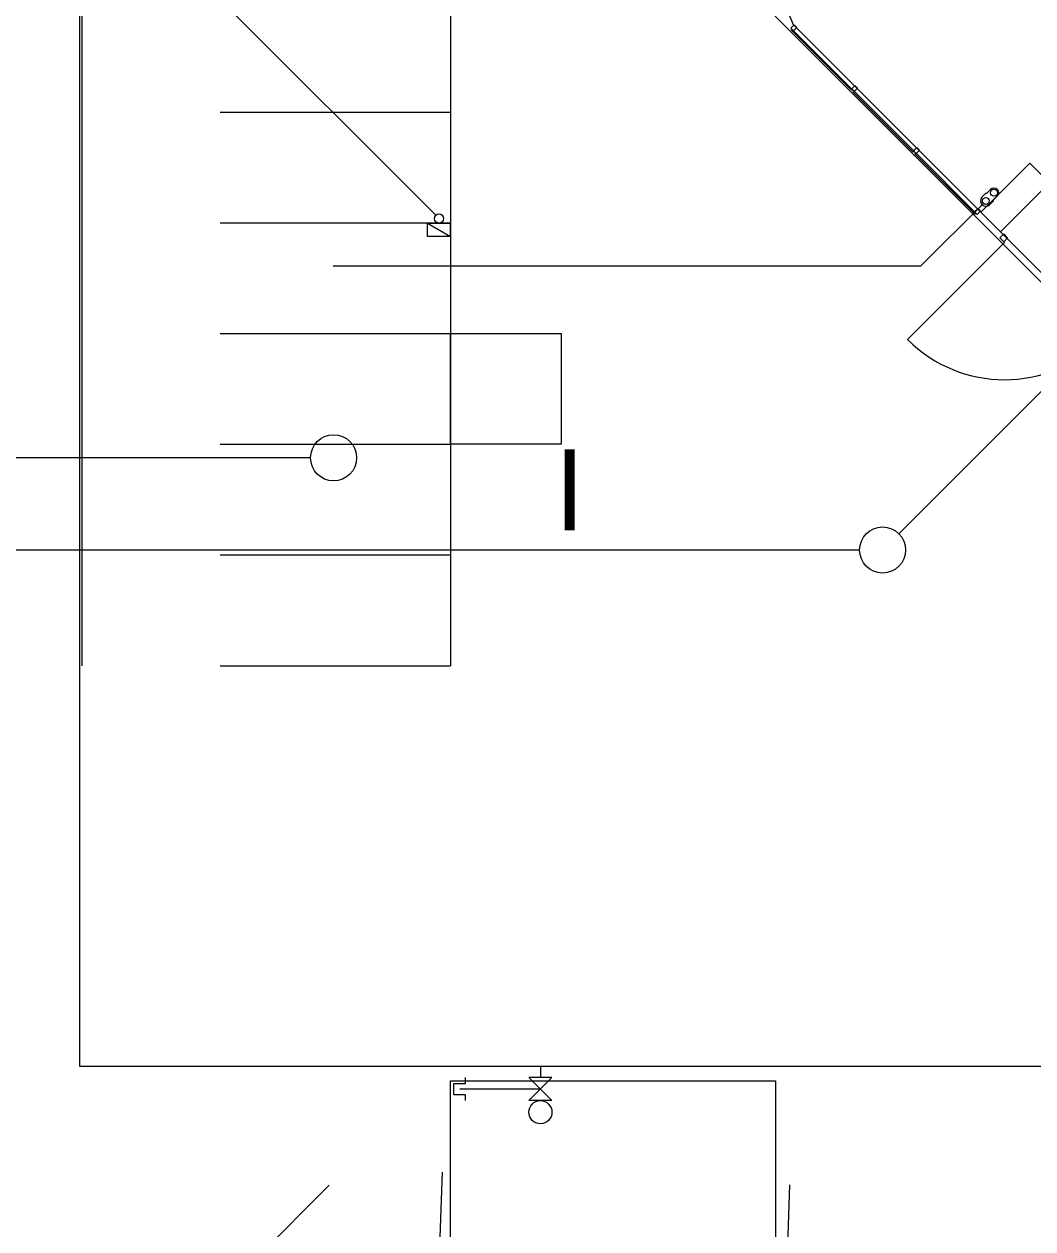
# Model space of a CAD drawing. Extents: x -264205 to -263615, y -1242401 to -1242031.
# Drawn here: x -263925.35 to -263903.46, y -1242253.67 to -1242227.54 of the extents above; entities that cross this region are included whole.
import ezdxf

# ---------------------------------------------------------------- set-up
doc = ezdxf.new("R2010")
doc.units = 0
doc.layers.add('KOORDINACNA_SITUACIA_DSP', color=7, linetype='Continuous')
doc.layers.add('PROJEKT_DRS_TDZ_VODOROVNE', color=7, linetype='Continuous')

msp = doc.modelspace()

# ---------------------------------------------------------------- linework, layer by layer
at = {"layer": 'KOORDINACNA_SITUACIA_DSP'}
for p, q in [((-263924.143, -1242185.14), (-263924.143, -1242250.14)), ((-263889.023, -1242221.253), (-263906.365, -1242238.596)), ((-263916.414, -1242231.691), (-263926.24, -1242221.865)), ((-263908.893, -1242226.995), (-263908.663, -1242227.55)), ((-263908.709, -1242227.631), (-263908.638, -1242227.56)), ((-263908.68, -1242227.659), (-263908.709, -1242227.631)), ((-263908.685, -1242227.654), (-263908.703, -1242227.672)), ((-263908.703, -1242227.672), (-263907.395, -1242228.98)), ((-263907.377, -1242228.963), (-263908.685, -1242227.654)), ((-263908.652, -1242227.688), (-263908.68, -1242227.659)), ((-263908.663, -1242227.55), (-263895.135, -1242241.078)), ((-263908.581, -1242227.617), (-263908.652, -1242227.688)), ((-263908.638, -1242227.56), (-263908.581, -1242227.617)), ((-263907.395, -1242228.98), (-263907.377, -1242228.963)), ((-263907.39, -1242228.95), (-263907.319, -1242228.879)), ((-263907.361, -1242228.978), (-263907.39, -1242228.95)), ((-263907.363, -1242229.012), (-263907.345, -1242228.994)), ((-263906.055, -1242230.32), (-263907.363, -1242229.012)), ((-263907.333, -1242229.007), (-263907.361, -1242228.978)), ((-263907.345, -1242228.994), (-263906.037, -1242230.303)), ((-263907.262, -1242228.936), (-263907.333, -1242229.007)), ((-263907.319, -1242228.879), (-263907.262, -1242228.936)), ((-263906.037, -1242230.303), (-263906.055, -1242230.32)), ((-263906.046, -1242230.294), (-263905.975, -1242230.223)), ((-263906.017, -1242230.322), (-263906.046, -1242230.294)), ((-263906.019, -1242230.356), (-263906.001, -1242230.338)), ((-263905.989, -1242230.351), (-263906.017, -1242230.322)), ((-263906.001, -1242230.338), (-263904.693, -1242231.647)), ((-263905.918, -1242230.28), (-263905.989, -1242230.351)), ((-263905.975, -1242230.223), (-263905.918, -1242230.28)), ((-263904.711, -1242231.664), (-263906.019, -1242230.356)), ((-263903.526, -1242230.561), (-263904.586, -1242231.622)), ((-263903.101, -1242230.985), (-263903.526, -1242230.561)), ((-263904.162, -1242232.046), (-263903.101, -1242230.985)), ((-263904.484, -1242231.218), (-263904.563, -1242231.296)), ((-263904.465, -1242231.218), (-263904.484, -1242231.218)), ((-263904.376, -1242231.13), (-263904.465, -1242231.218)), ((-263904.397, -1242231.462), (-263904.319, -1242231.383)), ((-263904.319, -1242231.383), (-263904.397, -1242231.462)), ((-263904.231, -1242231.275), (-263904.319, -1242231.364)), ((-263904.319, -1242231.364), (-263904.319, -1242231.383)), ((-263904.533, -1242231.432), (-263905.894, -1242232.793)), ((-263904.726, -1242231.613), (-263904.656, -1242231.543)), ((-263904.698, -1242231.642), (-263904.726, -1242231.613)), ((-263904.67, -1242231.67), (-263904.698, -1242231.642)), ((-263904.599, -1242231.599), (-263904.67, -1242231.67)), ((-263904.656, -1242231.543), (-263904.599, -1242231.599)), ((-263904.586, -1242231.622), (-263904.162, -1242232.046)), ((-263916.593, -1242231.862), (-263916.093, -1242231.862)), ((-263916.593, -1242232.152), (-263916.593, -1242231.862)), ((-263916.593, -1242231.862), (-263916.093, -1242232.152)), ((-263916.593, -1242231.862), (-263916.093, -1242232.152)), ((-263916.093, -1242231.862), (-263916.593, -1242231.862)), ((-263916.093, -1242231.862), (-263916.093, -1242232.152)), ((-263916.093, -1242232.152), (-263916.093, -1242231.862)), ((-263904.693, -1242231.647), (-263904.711, -1242231.664)), ((-263916.093, -1242232.152), (-263916.593, -1242232.152)), ((-263904.091, -1242232.093), (-263904.176, -1242232.178)), ((-263904.006, -1242232.178), (-263904.091, -1242232.093)), ((-263904.074, -1242232.281), (-263906.177, -1242234.384)), ((-263904.176, -1242232.178), (-263904.091, -1242232.263)), ((-263904.091, -1242232.263), (-263904.006, -1242232.178)), ((-263904.091, -1242232.263), (-263904.074, -1242232.281)), ((-263905.894, -1242232.793), (-263918.643, -1242232.793)), ((-263916.093, -1242234.257), (-263913.693, -1242234.257)), ((-263916.093, -1242236.657), (-263916.093, -1242234.257)), ((-263913.693, -1242234.257), (-263913.693, -1242236.657)), ((-263913.693, -1242236.657), (-263916.093, -1242236.657)), ((-263919.13, -1242236.949), (-263926.43, -1242236.949)), ((-263907.219, -1242238.949), (-263926.43, -1242238.949)), ((-263924.143, -1242250.14), (-263788.143, -1242250.14)), ((-263914.143, -1242250.14), (-263914.143, -1242250.39)), ((-263914.143, -1242250.14), (-263914.143, -1242250.39)), ((-263915.768, -1242250.515), (-263915.768, -1242250.39)), ((-263914.393, -1242250.39), (-263913.893, -1242250.89)), ((-263913.893, -1242250.39), (-263914.393, -1242250.39)), ((-263914.393, -1242250.89), (-263913.893, -1242250.39)), ((-263916.093, -1242254.982), (-263916.093, -1242250.458)), ((-263916.093, -1242250.458), (-263909.043, -1242250.458)), ((-263916.018, -1242250.515), (-263915.768, -1242250.515)), ((-263916.018, -1242250.765), (-263916.018, -1242250.515)), ((-263914.143, -1242250.64), (-263915.893, -1242250.64)), ((-263909.043, -1242250.458), (-263909.043, -1242254.982)), ((-263915.768, -1242250.765), (-263916.018, -1242250.765)), ((-263915.768, -1242250.89), (-263915.768, -1242250.765)), ((-263913.893, -1242250.89), (-263914.393, -1242250.89)), ((-263916.339, -1242254.492), (-263916.265, -1242252.443)), ((-263920.595, -1242254.592), (-263918.723, -1242252.72)), ((-263908.789, -1242254.387), (-263908.729, -1242252.715))]:
    msp.add_line(p, q, dxfattribs=at)
msp.add_lwpolyline([(-263794.893, -1242227.382), (-263808.968, -1242241.457), (-263894.968, -1242241.457), (-263909.043, -1242227.382), (-263909.043, -1242196.333), (-263914.143, -1242196.333), (-263914.143, -1242132.433), (-263909.043, -1242132.433), (-263909.043, -1242101.382), (-263894.968, -1242087.307), (-263808.968, -1242087.307), (-263794.893, -1242101.382), (-263794.893, -1242227.382)], dxfattribs=at)
for centre, radius in [((-263904.48, -1242231.379), 0.075), ((-263904.303, -1242231.202), 0.075), ((-263916.343, -1242231.762), 0.1), ((-263918.63, -1242236.949), 0.5), ((-263906.719, -1242238.949), 0.5), ((-263914.143, -1242251.14), 0.25)]:
    msp.add_circle(centre, radius, dxfattribs=at)
for centre, radius, start, end in [((-263904.303, -1242231.202), 0.103, 315, 135), ((-263904.48, -1242231.379), 0.117, 135, 315), ((-263904.074, -1242232.281), 2.975, 225.0001, 315.0001)]:
    msp.add_arc(centre, radius, start, end, dxfattribs=at)
at = {"layer": 'PROJEKT_DRS_TDZ_VODOROVNE'}
for p, q in [((-263924.088, -1242241.458), (-263924.093, -1242087.307)), ((-263916.093, -1242187.557), (-263916.093, -1242241.458)), ((-263921.093, -1242229.457), (-263916.093, -1242229.457)), ((-263921.093, -1242231.857), (-263916.093, -1242231.857)), ((-263921.093, -1242234.257), (-263916.093, -1242234.257)), ((-263921.093, -1242236.657), (-263916.093, -1242236.657)), ((-263921.093, -1242239.057), (-263916.093, -1242239.057)), ((-263921.093, -1242241.458), (-263916.093, -1242241.458))]:
    msp.add_line(p, q, dxfattribs=at)

# ---------------------------------------------------------------- texts
at = {"layer": 'KOORDINACNA_SITUACIA_DSP'}
msp.add_text('I', height=1.75, dxfattribs=at).set_placement((-263913.835, -1242238.519))

doc.saveas('drawing.dxf')
